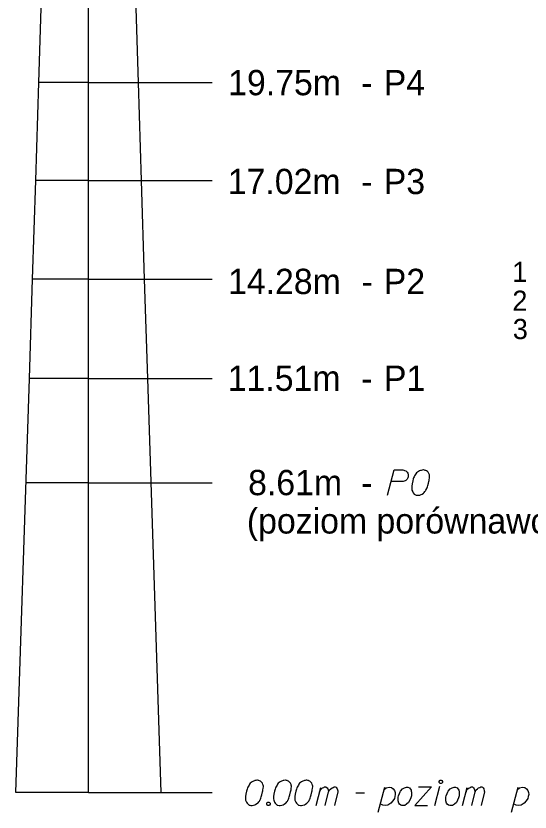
# Model space of a CAD drawing. Extents: x 138 to 264, y -75 to 121.
# Drawn here: x 170.97 to 178.09, y 55.45 to 66.47 of the extents above; entities that cross this region are included whole.
import ezdxf

# ---------------------------------------------------------------- set-up
doc = ezdxf.new("R2010")
doc.units = 0
doc.layers.add('Standard', color=7, linetype='Continuous')

msp = doc.modelspace()

# ---------------------------------------------------------------- linework, layer by layer
at = {"layer": 'Standard'}
for p, q in [((171.981, 55.72), (171.981, 75.804)), ((171.291, 65.552), (171.333, 66.911)), ((172.67, 65.552), (172.628, 66.911)), ((171.249, 64.194), (171.291, 65.552)), ((171.981, 65.552), (171.291, 65.552)), ((171.981, 65.552), (173.691, 65.552)), ((172.712, 64.194), (172.67, 65.552)), ((171.206, 62.826), (171.249, 64.194)), ((171.981, 64.194), (171.249, 64.194)), ((171.981, 64.194), (173.691, 64.194)), ((172.755, 62.826), (172.712, 64.194)), ((171.162, 61.451), (171.206, 62.826)), ((171.981, 62.826), (171.206, 62.826)), ((171.981, 62.826), (173.691, 62.826)), ((172.799, 61.451), (172.755, 62.826)), ((170.974, 55.72), (171.162, 61.451)), ((171.981, 61.451), (171.162, 61.451)), ((171.981, 61.451), (173.691, 61.451)), ((172.987, 55.72), (172.799, 61.451)), ((171.981, 60.005), (171.114, 60.005)), ((171.981, 60.005), (173.691, 60.005)), ((171.981, 55.72), (170.974, 55.72)), ((171.981, 55.72), (173.691, 55.72))]:
    msp.add_line(p, q, dxfattribs=at)
for points in [[(176.118, 59.836), (176.211, 60.186), (176.33, 60.186), (176.346, 60.183), (176.355, 60.18), (176.371, 60.172), (176.382, 60.164), (176.39, 60.153), (176.399, 60.139), (176.404, 60.12), (176.407, 60.103), (176.404, 60.089), (176.401, 60.078), (176.396, 60.067), (176.39, 60.059), (176.382, 60.048), (176.371, 60.04), (176.363, 60.034), (176.349, 60.029), (176.335, 60.026), (176.17, 60.026)], [(176.619, 60.186), (176.614, 60.186), (176.597, 60.183), (176.586, 60.18), (176.578, 60.177), (176.564, 60.172), (176.548, 60.164), (176.534, 60.155), (176.52, 60.144), (176.512, 60.133), (176.503, 60.12), (176.495, 60.106), (176.487, 60.089), (176.481, 60.078), (176.476, 60.062), (176.468, 60.034), (176.459, 59.993), (176.454, 59.96), (176.454, 59.929), (176.457, 59.907), (176.468, 59.883), (176.476, 59.869), (176.49, 59.852), (176.506, 59.841), (176.514, 59.838), (176.531, 59.836), (176.545, 59.836), (176.567, 59.838), (176.586, 59.844), (176.6, 59.852), (176.619, 59.866), (176.627, 59.874), (176.638, 59.885), (176.647, 59.896), (176.652, 59.905), (176.658, 59.918), (176.661, 59.924), (176.666, 59.938), (176.672, 59.954), (176.677, 59.971), (176.68, 59.982), (176.683, 59.99), (176.685, 60.001), (176.691, 60.026), (176.694, 60.04), (176.696, 60.053), (176.699, 60.073), (176.702, 60.097), (176.702, 60.106), (176.699, 60.117), (176.696, 60.128), (176.688, 60.144), (176.68, 60.155), (176.672, 60.164), (176.661, 60.172), (176.649, 60.177), (176.641, 60.18), (176.633, 60.183), (176.619, 60.186)], [(174.317, 55.889), (174.312, 55.889), (174.295, 55.886), (174.284, 55.884), (174.276, 55.881), (174.262, 55.875), (174.246, 55.867), (174.232, 55.859), (174.218, 55.848), (174.21, 55.837), (174.202, 55.823), (174.193, 55.809), (174.185, 55.793), (174.18, 55.782), (174.174, 55.765), (174.166, 55.738), (174.158, 55.696), (174.152, 55.663), (174.152, 55.633), (174.155, 55.611), (174.166, 55.586), (174.174, 55.572), (174.188, 55.556), (174.204, 55.545), (174.213, 55.542), (174.229, 55.539), (174.243, 55.539), (174.265, 55.542), (174.284, 55.548), (174.298, 55.556), (174.317, 55.57), (174.326, 55.578), (174.337, 55.589), (174.345, 55.6), (174.35, 55.608), (174.356, 55.622), (174.359, 55.627), (174.364, 55.641), (174.37, 55.658), (174.375, 55.674), (174.378, 55.685), (174.381, 55.694), (174.384, 55.705), (174.389, 55.729), (174.392, 55.743), (174.395, 55.757), (174.397, 55.776), (174.4, 55.801), (174.4, 55.809), (174.397, 55.82), (174.395, 55.831), (174.386, 55.848), (174.378, 55.859), (174.37, 55.867), (174.359, 55.875), (174.348, 55.881), (174.339, 55.884), (174.331, 55.886), (174.317, 55.889)], [(174.706, 55.889), (174.7, 55.889), (174.684, 55.886), (174.673, 55.884), (174.665, 55.881), (174.651, 55.875), (174.634, 55.867), (174.621, 55.859), (174.607, 55.848), (174.598, 55.837), (174.59, 55.823), (174.582, 55.809), (174.574, 55.793), (174.568, 55.782), (174.563, 55.765), (174.554, 55.738), (174.546, 55.696), (174.541, 55.663), (174.541, 55.633), (174.543, 55.611), (174.554, 55.586), (174.563, 55.572), (174.576, 55.556), (174.593, 55.545), (174.601, 55.542), (174.618, 55.539), (174.632, 55.539), (174.654, 55.542), (174.673, 55.548), (174.687, 55.556), (174.706, 55.57), (174.714, 55.578), (174.725, 55.589), (174.733, 55.6), (174.739, 55.608), (174.745, 55.622), (174.747, 55.627), (174.753, 55.641), (174.758, 55.658), (174.764, 55.674), (174.767, 55.685), (174.769, 55.694), (174.772, 55.705), (174.778, 55.729), (174.78, 55.743), (174.783, 55.757), (174.786, 55.776), (174.789, 55.801), (174.789, 55.809), (174.786, 55.82), (174.783, 55.831), (174.775, 55.848), (174.767, 55.859), (174.758, 55.867), (174.747, 55.875), (174.736, 55.881), (174.728, 55.884), (174.72, 55.886), (174.706, 55.889)], [(175.001, 55.889), (174.995, 55.889), (174.979, 55.886), (174.968, 55.884), (174.959, 55.881), (174.946, 55.875), (174.929, 55.867), (174.915, 55.859), (174.902, 55.848), (174.893, 55.837), (174.885, 55.823), (174.877, 55.809), (174.868, 55.793), (174.863, 55.782), (174.857, 55.765), (174.849, 55.738), (174.841, 55.696), (174.835, 55.663), (174.835, 55.633), (174.838, 55.611), (174.849, 55.586), (174.857, 55.572), (174.871, 55.556), (174.888, 55.545), (174.896, 55.542), (174.913, 55.539), (174.926, 55.539), (174.948, 55.542), (174.968, 55.548), (174.982, 55.556), (175.001, 55.57), (175.009, 55.578), (175.02, 55.589), (175.028, 55.6), (175.034, 55.608), (175.039, 55.622), (175.042, 55.627), (175.048, 55.641), (175.053, 55.658), (175.059, 55.674), (175.061, 55.685), (175.064, 55.694), (175.067, 55.705), (175.072, 55.729), (175.075, 55.743), (175.078, 55.757), (175.081, 55.776), (175.083, 55.801), (175.083, 55.809), (175.081, 55.82), (175.078, 55.831), (175.07, 55.848), (175.061, 55.859), (175.053, 55.867), (175.042, 55.875), (175.031, 55.881), (175.023, 55.884), (175.015, 55.886), (175.001, 55.889)], [(175.13, 55.539), (175.194, 55.79)], [(175.177, 55.724), (175.191, 55.754), (175.205, 55.771), (175.221, 55.782), (175.238, 55.79), (175.249, 55.796), (175.265, 55.796), (175.271, 55.793), (175.282, 55.782), (175.293, 55.768), (175.301, 55.743), (175.304, 55.729), (175.318, 55.754), (175.334, 55.771), (175.351, 55.782), (175.367, 55.79), (175.381, 55.796), (175.395, 55.796), (175.406, 55.793), (175.414, 55.782), (175.422, 55.768), (175.431, 55.743), (175.433, 55.729), (175.387, 55.539)], [(175.988, 55.448), (176.081, 55.793)], [(176.073, 55.762), (176.101, 55.785), (176.142, 55.793), (176.175, 55.787), (176.197, 55.771), (176.214, 55.749), (176.225, 55.718), (176.227, 55.691), (176.222, 55.666), (176.214, 55.636), (176.192, 55.603), (176.164, 55.572), (176.123, 55.545), (176.087, 55.539), (176.054, 55.542), (176.018, 55.561)], [(176.382, 55.793), (176.401, 55.793), (176.423, 55.782), (176.445, 55.751), (176.448, 55.738), (176.451, 55.724), (176.451, 55.713), (176.451, 55.672), (176.442, 55.644), (176.429, 55.611), (176.412, 55.583), (176.384, 55.559), (176.36, 55.539), (176.318, 55.539), (176.302, 55.545), (176.285, 55.559), (176.277, 55.572), (176.266, 55.605), (176.266, 55.655), (176.271, 55.672), (176.283, 55.707), (176.294, 55.727), (176.299, 55.738), (176.327, 55.768), (176.354, 55.785), (176.382, 55.793)], [(176.547, 55.798), (176.726, 55.798), (176.497, 55.539), (176.674, 55.539)], [(176.773, 55.539), (176.845, 55.807)], [(176.85, 55.889), (176.864, 55.889), (176.872, 55.884), (176.881, 55.873), (176.881, 55.859), (176.872, 55.848), (176.864, 55.842), (176.85, 55.842), (176.842, 55.848), (176.834, 55.859), (176.834, 55.873), (176.842, 55.884), (176.85, 55.889)], [(177.043, 55.793), (177.062, 55.793), (177.084, 55.782), (177.107, 55.751), (177.109, 55.738), (177.112, 55.724), (177.112, 55.713), (177.112, 55.672), (177.104, 55.644), (177.09, 55.611), (177.073, 55.583), (177.046, 55.559), (177.021, 55.539), (176.98, 55.539), (176.963, 55.545), (176.947, 55.559), (176.938, 55.572), (176.927, 55.605), (176.927, 55.655), (176.933, 55.672), (176.944, 55.707), (176.955, 55.727), (176.96, 55.738), (176.988, 55.768), (177.016, 55.785), (177.043, 55.793)], [(177.159, 55.539), (177.222, 55.79)], [(177.206, 55.724), (177.219, 55.754), (177.233, 55.771), (177.25, 55.782), (177.266, 55.79), (177.277, 55.796), (177.294, 55.796), (177.299, 55.793), (177.31, 55.782), (177.321, 55.768), (177.33, 55.743), (177.332, 55.729), (177.346, 55.754), (177.363, 55.771), (177.379, 55.782), (177.396, 55.79), (177.41, 55.796), (177.423, 55.796), (177.434, 55.793), (177.443, 55.782), (177.451, 55.768), (177.459, 55.743), (177.462, 55.729), (177.415, 55.539)], [(177.834, 55.448), (177.928, 55.793)], [(177.919, 55.762), (177.947, 55.785), (177.988, 55.793), (178.021, 55.787), (178.043, 55.771), (178.06, 55.749), (178.071, 55.718), (178.074, 55.691), (178.068, 55.666), (178.06, 55.636), (178.038, 55.603), (178.01, 55.572), (177.969, 55.545), (177.933, 55.539), (177.9, 55.542), (177.864, 55.561)], [(175.257, 55.539), (175.304, 55.729)], [(175.682, 55.716), (175.8, 55.716)], [(177.286, 55.539), (177.332, 55.729)], [(174.463, 55.586), (174.477, 55.586), (174.485, 55.581), (174.494, 55.57), (174.494, 55.556), (174.485, 55.545), (174.477, 55.539), (174.463, 55.539), (174.455, 55.545), (174.447, 55.556), (174.447, 55.57), (174.455, 55.581), (174.463, 55.586)]]:
    msp.add_lwpolyline(points, dxfattribs=at)

# ---------------------------------------------------------------- texts
for s, height, p in [('19.75m', 0.35, (173.913, 65.374)), ('P4', 0.35, (176.067, 65.374)), ('-', 0.35, (175.756, 65.374)), ('17.02m', 0.35, (173.908, 64.005)), ('P3', 0.35, (176.067, 64.005)), ('-', 0.35, (175.756, 64.005)), ('1', 0.28, (177.845, 62.788)), ('14.28m', 0.35, (173.911, 62.621)), ('P2', 0.35, (176.067, 62.621)), ('-', 0.35, (175.758, 62.621)), ('2', 0.28, (177.848, 62.389)), ('3', 0.28, (177.854, 61.997)), ('11.51m', 0.35, (173.907, 61.281)), ('P1', 0.35, (176.069, 61.281)), ('-', 0.35, (175.756, 61.281)), ('8.61m', 0.35, (174.189, 59.836)), ('-', 0.35, (175.756, 59.836)), ('(poziom porównawczy)', 0.35, (174.172, 59.305))]:
    msp.add_text(s, height=height, dxfattribs=at).set_placement(p)

doc.saveas('drawing.dxf')
